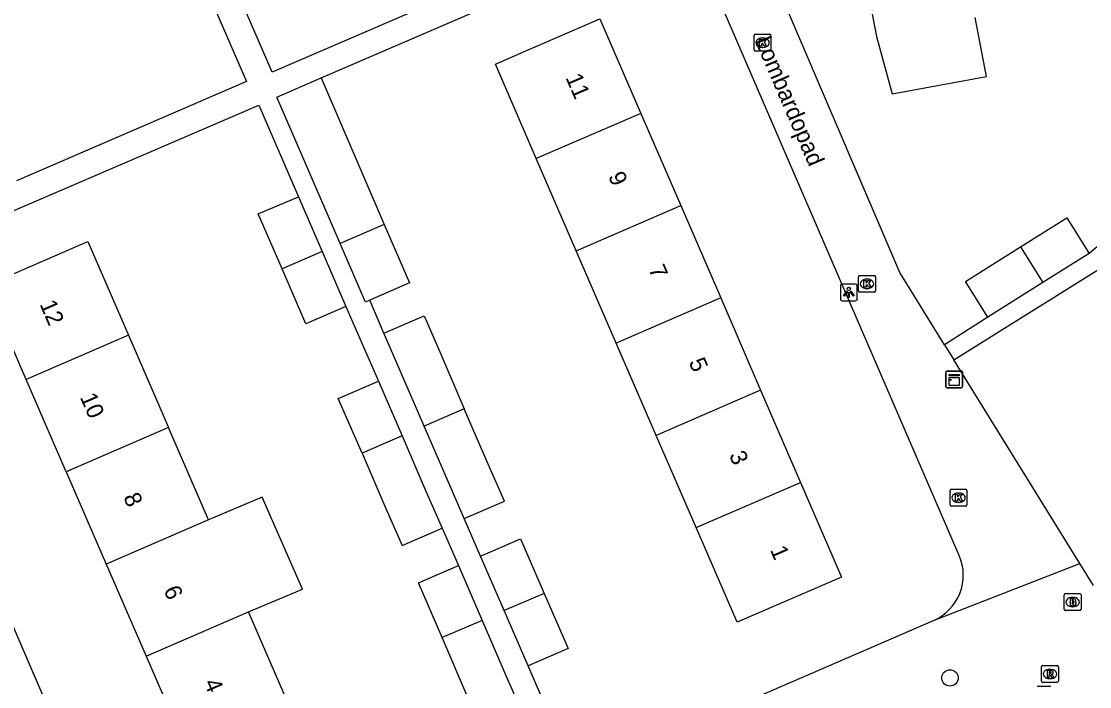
# Model space of a CAD drawing. Extents: x 159353 to 160616, y 385893 to 387321.
# Drawn here: x 159645.1 to 159708.8, y 386260.9 to 386300.6 of the extents above; entities that cross this region are included whole.
import ezdxf

# ---------------------------------------------------------------- set-up
doc = ezdxf.new("R2010")
doc.units = 0
for name, color, linetype in [('IMGEO_Boom', 7, 'Continuous'), ('IMGEO_Brandkraan', 7, 'Continuous'), ('IMGEO_Kast', 7, 'Continuous'), ('IMGEO_Kolk', 7, 'Continuous'), ('IMGEO_Lichtpunt', 7, 'Continuous'), ('IMGEO_Openbare_ruimte_label', 7, 'Continuous'), ('IMGEO_Pand', 7, 'Continuous'), ('IMGEO_Pand_nummerreeks', 7, 'Continuous'), ('IMGEO_Rioolput', 7, 'Continuous'), ('IMGEO_Voetpad_open', 7, 'Continuous')]:
    doc.layers.add(name, color=color, linetype=linetype)

msp = doc.modelspace()

# ---------------------------------------------------------------- linework, layer by layer
at = {"layer": 'IMGEO_Boom'}
msp.add_circle((159700.455, 386261.45), 0.489, dxfattribs=at)
at = {"layer": 'IMGEO_Brandkraan'}
for p, q in [((159707.263, 386265.547), (159707.263, 386266.399)), ((159707.338, 386266.473), (159708.19, 386266.473)), ((159707.751, 386266.253), (159707.776, 386266.253)), ((159708.264, 386266.399), (159708.264, 386265.547)), ((159708.19, 386265.473), (159707.338, 386265.473)), ((159707.774, 386265.693), (159707.749, 386265.693))]:
    msp.add_line(p, q, dxfattribs=at)
for points in [[(159707.263, 386265.547), (159707.263, 386266.399)], [(159707.338, 386266.473), (159708.19, 386266.473)], [(159707.611, 386266.173), (159707.611, 386265.773), (159707.824, 386265.773)], [(159707.842, 386266.173), (159707.611, 386266.173)], [(159707.79, 386266.092), (159707.736, 386266.092), (159707.736, 386266.016)], [(159708.264, 386266.399), (159708.264, 386265.547)], [(159708.19, 386265.473), (159707.338, 386265.473)], [(159707.736, 386266.016), (159707.789, 386266.016)], [(159707.798, 386265.94), (159707.736, 386265.94), (159707.736, 386265.859)], [(159707.736, 386265.859), (159707.798, 386265.859)]]:
    msp.add_lwpolyline(points, dxfattribs=at)
for centre, radius, start, end in [((159707.34, 386266.397), 0.0765, 91.55205, 178.44795), ((159707.34, 386266.397), 0.0765, 91.55205, 178.44795), ((159707.791, 386266.054), 0.0379, 267.82845, 90.93552), ((159707.846, 386266.028), 0.145, 59.4692, 91.53667), ((159707.871, 386266.075), 0.0922, 285.51372, 58.15012), ((159708.188, 386266.397), 0.0765, 1.55205, 88.44795), ((159708.188, 386266.397), 0.0765, 1.55205, 88.44795), ((159707.34, 386265.549), 0.0765, 181.55205, 268.44795), ((159707.34, 386265.549), 0.0765, 181.55205, 268.44795), ((159707.799, 386265.899), 0.0404, 269.87594, 90.50774), ((159707.83, 386266.024), 0.251, 268.66757, 293.53466), ((159707.876, 386265.883), 0.105, 301.31148, 78.98903), ((159708.188, 386265.549), 0.0765, 271.55205, 358.44795), ((159708.188, 386265.549), 0.0765, 271.55205, 358.44795)]:
    msp.add_arc(centre, radius, start, end, dxfattribs=at)
for centre, major_axis, ratio, start_param, end_param in [((159707.75, 386265.973), (-0.387, 0.002), 0.722429, 4.712389, 7.853982), ((159707.775, 386265.973), (-0.39, 0.002), 0.717154, 1.570796, 4.712389)]:
    msp.add_ellipse(centre, major_axis=major_axis, ratio=ratio, start_param=start_param, end_param=end_param, dxfattribs=at)
at = {"layer": 'IMGEO_Kast'}
for p, q in [((159700.204, 386278.825), (159700.204, 386279.666)), ((159700.204, 386279.666), (159700.204, 386278.825)), ((159700.279, 386279.75), (159701.12, 386279.75)), ((159701.12, 386279.75), (159700.279, 386279.75)), ((159701.204, 386279.675), (159701.204, 386278.834)), ((159701.204, 386278.834), (159701.204, 386279.675)), ((159701.129, 386278.75), (159700.288, 386278.75)), ((159700.288, 386278.75), (159701.129, 386278.75))]:
    msp.add_line(p, q, dxfattribs=at)
for points in [[(159700.399, 386279.54), (159700.999, 386279.54), (159700.999, 386279.455), (159700.399, 386279.455), (159700.399, 386279.54)], [(159700.399, 386279.365), (159700.999, 386279.365), (159700.999, 386278.876), (159700.399, 386278.876), (159700.399, 386279.365)]]:
    msp.add_lwpolyline(points, dxfattribs=at)
msp.add_circle((159700.483, 386279.214), 0.0377, dxfattribs=at)
for centre, start, end in [((159700.282, 386279.672), 92.4484, 184.28452), ((159700.282, 386279.672), 92.4484, 184.28452), ((159701.126, 386279.672), 2.4484, 94.28452), ((159701.126, 386279.672), 2.4484, 94.28452), ((159700.282, 386278.828), 182.4484, 274.28452), ((159700.282, 386278.828), 182.4484, 274.28452), ((159701.126, 386278.828), 272.4484, 4.28452), ((159701.126, 386278.828), 272.4484, 4.28452)]:
    msp.add_arc(centre, 0.0779, start, end, dxfattribs=at)
at = {"layer": 'IMGEO_Kolk'}
for p, q in [((159688.854, 386299.828), (159689.706, 386299.828)), ((159688.779, 386298.902), (159688.779, 386299.754)), ((159689.267, 386299.608), (159689.292, 386299.608)), ((159689.78, 386299.754), (159689.78, 386298.902)), ((159689.706, 386298.828), (159688.854, 386298.828)), ((159689.29, 386299.048), (159689.265, 386299.048)), ((159695.005, 386284.521), (159695.005, 386285.373)), ((159695.08, 386285.447), (159695.932, 386285.447)), ((159695.493, 386285.227), (159695.518, 386285.227)), ((159696.006, 386285.373), (159696.006, 386284.521)), ((159695.516, 386284.667), (159695.491, 386284.667)), ((159695.932, 386284.447), (159695.08, 386284.447)), ((159700.461, 386271.769), (159700.461, 386272.621)), ((159700.536, 386272.695), (159701.388, 386272.695)), ((159700.949, 386272.475), (159700.974, 386272.475)), ((159701.462, 386272.621), (159701.462, 386271.769)), ((159700.972, 386271.915), (159700.947, 386271.915)), ((159701.388, 386271.695), (159700.536, 386271.695))]:
    msp.add_line(p, q, dxfattribs=at)
for points in [[(159688.854, 386299.828), (159689.706, 386299.828)], [(159688.779, 386298.902), (159688.779, 386299.754)], [(159689.1, 386299.528), (159689.223, 386299.528), (159689.223, 386299.377), (159689.353, 386299.528), (159689.517, 386299.528), (159689.371, 386299.377), (159689.524, 386299.128), (159689.372, 386299.128), (159689.287, 386299.292), (159689.223, 386299.225), (159689.223, 386299.128), (159689.1, 386299.128), (159689.1, 386299.528)], [(159689.78, 386299.754), (159689.78, 386298.902)], [(159689.706, 386298.828), (159688.854, 386298.828)], [(159695.005, 386284.521), (159695.005, 386285.373)], [(159695.08, 386285.447), (159695.932, 386285.447)], [(159695.326, 386285.147), (159695.449, 386285.147), (159695.449, 386284.996), (159695.579, 386285.147), (159695.743, 386285.147), (159695.597, 386284.996), (159695.75, 386284.747), (159695.598, 386284.747), (159695.513, 386284.911), (159695.449, 386284.844), (159695.449, 386284.747), (159695.326, 386284.747), (159695.326, 386285.147)], [(159696.006, 386285.373), (159696.006, 386284.521)], [(159695.932, 386284.447), (159695.08, 386284.447)], [(159700.461, 386271.769), (159700.461, 386272.621)], [(159700.536, 386272.695), (159701.388, 386272.695)], [(159700.782, 386272.395), (159700.905, 386272.395), (159700.905, 386272.244), (159701.035, 386272.395), (159701.199, 386272.395), (159701.053, 386272.244), (159701.206, 386271.995), (159701.054, 386271.995), (159700.969, 386272.159), (159700.905, 386272.092), (159700.905, 386271.995), (159700.782, 386271.995), (159700.782, 386272.395)], [(159701.462, 386272.621), (159701.462, 386271.769)], [(159701.388, 386271.695), (159700.536, 386271.695)]]:
    msp.add_lwpolyline(points, dxfattribs=at)
for centre, start, end in [((159688.856, 386299.752), 91.55205, 178.44795), ((159688.856, 386299.752), 91.55205, 178.44795), ((159689.704, 386299.752), 1.55205, 88.44795), ((159689.704, 386299.752), 1.55205, 88.44795), ((159688.856, 386298.904), 181.55205, 268.44795), ((159688.856, 386298.904), 181.55205, 268.44795), ((159689.704, 386298.904), 271.55205, 358.44795), ((159689.704, 386298.904), 271.55205, 358.44795), ((159695.082, 386285.371), 91.55205, 178.44795), ((159695.082, 386285.371), 91.55205, 178.44795), ((159695.93, 386285.371), 1.55205, 88.44795), ((159695.93, 386285.371), 1.55205, 88.44795), ((159695.082, 386284.523), 181.55205, 268.44795), ((159695.082, 386284.523), 181.55205, 268.44795), ((159695.93, 386284.523), 271.55205, 358.44795), ((159695.93, 386284.523), 271.55205, 358.44795), ((159700.538, 386272.619), 91.55205, 178.44795), ((159700.538, 386272.619), 91.55205, 178.44795), ((159701.386, 386272.619), 1.55205, 88.44795), ((159701.386, 386272.619), 1.55205, 88.44795), ((159700.538, 386271.771), 181.55205, 268.44795), ((159700.538, 386271.771), 181.55205, 268.44795), ((159701.386, 386271.771), 271.55205, 358.44795), ((159701.386, 386271.771), 271.55205, 358.44795)]:
    msp.add_arc(centre, 0.0765, start, end, dxfattribs=at)
for centre, major_axis, ratio, start_param, end_param in [((159689.266, 386299.328), (-0.387, 0.002), 0.722429, 4.712389, 7.853982), ((159689.291, 386299.328), (-0.39, 0.002), 0.717154, 1.570796, 4.712389), ((159695.492, 386284.947), (-0.387, 0.002), 0.722429, 4.712389, 7.853982), ((159695.517, 386284.947), (-0.39, 0.002), 0.717154, 1.570796, 4.712389), ((159700.948, 386272.195), (-0.387, 0.002), 0.722429, 4.712389, 7.853982), ((159700.973, 386272.195), (-0.39, 0.002), 0.717154, 1.570796, 4.712389)]:
    msp.add_ellipse(centre, major_axis=major_axis, ratio=ratio, start_param=start_param, end_param=end_param, dxfattribs=at)
at = {"layer": 'IMGEO_Lichtpunt'}
for p, q in [((159693.924, 386284.842), (159693.924, 386284.035)), ((159693.924, 386284.842), (159693.924, 386284.035)), ((159694.826, 386284.937), (159694.018, 386284.937)), ((159694.826, 386284.937), (159694.018, 386284.937)), ((159694.92, 386284.035), (159694.92, 386284.842)), ((159694.92, 386284.035), (159694.92, 386284.842)), ((159694.018, 386283.941), (159694.826, 386283.941)), ((159694.018, 386283.941), (159694.826, 386283.941)), ((159706.455, 386260.928), (159705.647, 386260.928)), ((159706.455, 386260.928), (159705.647, 386260.928))]:
    msp.add_line(p, q, dxfattribs=at)
for points in [[(159694.298, 386284.506), (159694.337, 386284.478), (159694.149, 386284.216), (159694.111, 386284.243), (159694.298, 386284.506)], [(159694.51, 386284.478), (159694.548, 386284.505), (159694.735, 386284.243), (159694.696, 386284.215), (159694.51, 386284.478)], [(159694.4, 386284.458), (159694.447, 386284.458), (159694.447, 386284.136), (159694.4, 386284.136), (159694.4, 386284.458)]]:
    msp.add_lwpolyline(points, dxfattribs=at)
msp.add_circle((159694.423, 386284.64), 0.0994, dxfattribs=at)
for centre, start, end in [((159694.018, 386284.842), 90, 180), ((159694.018, 386284.842), 90, 180), ((159694.826, 386284.842), 0, 90), ((159694.826, 386284.842), 0, 90), ((159694.018, 386284.035), 180, 270), ((159694.018, 386284.035), 180, 270), ((159694.826, 386284.035), 270, 0), ((159694.826, 386284.035), 270, 360)]:
    msp.add_arc(centre, 0.0946, start, end, dxfattribs=at)
at = {"layer": 'IMGEO_Pand'}
for points in [[(159700.678, 386307.441), (159694.802, 386306.304), (159696.082, 386299.697), (159697, 386296.28), (159702.621, 386297.319), (159701.958, 386300.826)], [(159675.796, 386292.416), (159673.355, 386298.054), (159674.994, 386298.764), (159679.582, 386300.75), (159682.023, 386295.112)], [(159664.109, 386287.356), (159660.337, 386296.088), (159662.967, 386297.224)], [(159662.967, 386297.224), (159666.737, 386288.494)], [(159682.023, 386295.112), (159675.796, 386292.416)], [(159682.023, 386295.112), (159684.404, 386289.61)], [(159678.178, 386286.914), (159675.796, 386292.416)], [(159660.638, 386285.851), (159659.226, 386289.113), (159661.612, 386290.145)], [(159661.612, 386290.145), (159663.023, 386286.884)], [(159678.178, 386286.914), (159684.404, 386289.61)], [(159684.404, 386289.61), (159686.786, 386284.108)], [(159666.737, 386288.494), (159664.109, 386287.356)], [(159666.737, 386288.494), (159668.247, 386284.999), (159665.868, 386283.972)], [(159704.664, 386287.155), (159707.422, 386288.882), (159708.755, 386286.755)], [(159645.381, 386279.239), (159642.958, 386284.827), (159647.546, 386286.816), (159649.064, 386287.474), (159651.487, 386281.885)], [(159665.868, 386283.972), (159665.617, 386283.864), (159664.109, 386287.356)], [(159702.704, 386282.965), (159701.371, 386285.092), (159704.664, 386287.155)], [(159704.664, 386287.155), (159705.997, 386285.027)], [(159663.023, 386286.884), (159660.638, 386285.851)], [(159663.023, 386286.884), (159664.448, 386283.593)], [(159680.559, 386281.413), (159678.178, 386286.914)], [(159708.755, 386286.755), (159705.997, 386285.027)], [(159664.448, 386283.593), (159662.062, 386282.561), (159660.638, 386285.851)], [(159705.997, 386285.027), (159702.704, 386282.965)], [(159686.786, 386284.108), (159680.559, 386281.413)], [(159686.786, 386284.108), (159689.167, 386278.607)], [(159666.716, 386282.012), (159669.102, 386283.045), (159670.095, 386280.751), (159671.505, 386277.494)], [(159669.119, 386276.462), (159667.709, 386279.718), (159666.716, 386282.012)], [(159651.487, 386281.885), (159645.381, 386279.239)], [(159651.487, 386281.885), (159653.872, 386276.384)], [(159682.941, 386275.911), (159680.559, 386281.413)], [(159647.765, 386273.739), (159645.381, 386279.239)], [(159665.407, 386274.85), (159663.995, 386278.112), (159666.381, 386279.144)], [(159666.381, 386279.144), (159667.792, 386275.883)], [(159689.167, 386278.607), (159682.941, 386275.911)], [(159689.167, 386278.607), (159691.549, 386273.105)], [(159671.505, 386277.494), (159669.119, 386276.462)], [(159671.504, 386270.951), (159673.89, 386271.984), (159672.931, 386274.199), (159671.505, 386277.494)], [(159653.872, 386276.384), (159647.765, 386273.739)], [(159656.256, 386270.884), (159653.872, 386276.384)], [(159671.504, 386270.951), (159670.545, 386273.166), (159669.119, 386276.462)], [(159667.792, 386275.883), (159665.407, 386274.85)], [(159667.792, 386275.883), (159669.217, 386272.592), (159670.178, 386270.372)], [(159685.322, 386270.41), (159682.941, 386275.911)], [(159665.407, 386274.85), (159666.831, 386271.56), (159667.793, 386269.339), (159670.178, 386270.372)], [(159647.765, 386273.739), (159650.15, 386268.238)], [(159691.549, 386273.105), (159693.99, 386267.465), (159687.764, 386264.77), (159685.777, 386269.359), (159685.322, 386270.41)], [(159685.322, 386270.41), (159691.549, 386273.105)], [(159658.641, 386265.383), (159661.859, 386266.75), (159659.462, 386272.227), (159656.256, 386270.884)], [(159656.256, 386270.884), (159650.15, 386268.238)], [(159672.472, 386268.715), (159674.858, 386269.748), (159676.268, 386266.491)], [(159673.882, 386265.459), (159672.472, 386268.715)], [(159650.15, 386268.238), (159652.534, 386262.738)], [(159670.176, 386263.849), (159668.764, 386267.111), (159671.15, 386268.143)], [(159671.15, 386268.143), (159672.561, 386264.882)], [(159676.268, 386266.491), (159673.882, 386265.459)], [(159676.268, 386266.491), (159677.694, 386263.196), (159675.308, 386262.163)], [(159675.308, 386262.163), (159673.882, 386265.459)], [(159652.534, 386262.738), (159658.641, 386265.383)], [(159661.025, 386259.883), (159658.641, 386265.383)], [(159672.561, 386264.882), (159670.176, 386263.849)], [(159672.561, 386264.882), (159673.986, 386261.591), (159676.792, 386255.192)], [(159676.792, 386255.192), (159674.437, 386254.151), (159671.6, 386260.559), (159670.176, 386263.849)], [(159652.534, 386262.738), (159654.919, 386257.237)]]:
    msp.add_lwpolyline(points, dxfattribs=at)
at = {"layer": 'IMGEO_Rioolput'}
for p, q in [((159705.911, 386261.258), (159705.911, 386262.11)), ((159705.986, 386262.184), (159706.838, 386262.184)), ((159706.399, 386261.964), (159706.424, 386261.964)), ((159706.912, 386262.11), (159706.912, 386261.258)), ((159706.838, 386261.184), (159705.986, 386261.184)), ((159706.422, 386261.404), (159706.397, 386261.404))]:
    msp.add_line(p, q, dxfattribs=at)
for points in [[(159705.911, 386261.258), (159705.911, 386262.11)], [(159705.986, 386262.184), (159706.838, 386262.184)], [(159706.5, 386261.882), (159706.248, 386261.884), (159706.248, 386261.484)], [(159706.248, 386261.484), (159706.372, 386261.484), (159706.372, 386261.646), (159706.383, 386261.646)], [(159706.426, 386261.803), (159706.372, 386261.803), (159706.372, 386261.722)], [(159706.372, 386261.722), (159706.424, 386261.722)], [(159706.43, 386261.617), (159706.501, 386261.484), (159706.641, 386261.484), (159706.576, 386261.61)], [(159706.912, 386262.11), (159706.912, 386261.258)], [(159706.838, 386261.184), (159705.986, 386261.184)]]:
    msp.add_lwpolyline(points, dxfattribs=at)
for centre, radius, start, end in [((159705.988, 386262.108), 0.0765, 91.55205, 178.44795), ((159705.988, 386262.108), 0.0765, 91.55205, 178.44795), ((159706.382, 386261.593), 0.0533, 26.02933, 88.69889), ((159706.408, 386261.911), 0.19, 274.7715, 282.96867), ((159706.432, 386261.707), 0.0964, 77.00612, 93.18647), ((159706.446, 386261.764), 0.0378, 276.66336, 79.67722), ((159706.499, 386261.772), 0.109, 350.36119, 89.41601), ((159706.497, 386261.772), 0.112, 277.58423, 350.98172), ((159706.481, 386261.557), 0.108, 29.51342, 73.79051), ((159706.836, 386262.108), 0.0765, 1.55205, 88.44795), ((159706.836, 386262.108), 0.0765, 1.55205, 88.44795), ((159705.988, 386261.26), 0.0765, 181.55205, 268.44795), ((159705.988, 386261.26), 0.0765, 181.55205, 268.44795), ((159706.836, 386261.26), 0.0765, 271.55205, 358.44795), ((159706.836, 386261.26), 0.0765, 271.55205, 358.44795)]:
    msp.add_arc(centre, radius, start, end, dxfattribs=at)
for centre, major_axis, ratio, start_param, end_param in [((159706.398, 386261.684), (-0.387, 0.002), 0.722429, 4.712389, 7.853982), ((159706.423, 386261.684), (-0.39, 0.002), 0.717154, 1.570796, 4.712389)]:
    msp.add_ellipse(centre, major_axis=major_axis, ratio=ratio, start_param=start_param, end_param=end_param, dxfattribs=at)
at = {"layer": 'IMGEO_Voetpad_open'}
for points in [[(159684.092, 386307.943), (159660.056, 386297.569), (159659.735, 386298.309), (159657.843, 386302.678)], [(159662.967, 386297.224), (159684.675, 386306.593)], [(159701.006, 386268.753), (159684.675, 386306.593)], [(159700.131, 386281.311), (159697.471, 386285.615), (159689.082, 386305.236)], [(159656.34, 386302.053), (159658.516, 386297.013), (159644.802, 386291.091)], [(159635.593, 386285.426), (159659.247, 386295.61), (159661.612, 386290.145)], [(159712.133, 386289.552), (159708.755, 386286.755)], [(159700.683, 386280.417), (159711.275, 386287.034)], [(159635.593, 386285.426), (159650.846, 386250), (159651.931, 386247.481)], [(159666.716, 386282.012), (159665.868, 386283.972)], [(159664.448, 386283.593), (159666.381, 386279.144)], [(159702.704, 386282.965), (159700.131, 386281.311)], [(159700.131, 386281.311), (159700.683, 386280.417)], [(159708.189, 386268.272), (159700.683, 386280.417)], [(159672.472, 386268.715), (159671.504, 386270.951)], [(159670.178, 386270.372), (159671.15, 386268.143)], [(159699.462, 386264.867), (159708.189, 386268.272)], [(159709.001, 386266.959), (159708.189, 386268.272)], [(159678.131, 386255.638), (159699.462, 386264.867)], [(159678.131, 386255.638), (159675.308, 386262.163)]]:
    msp.add_lwpolyline(points, dxfattribs=at)
msp.add_arc((159698.292, 386267.582), 2.956, 293.31902, 23.34278, dxfattribs=at)

# ---------------------------------------------------------------- texts
at = {"layer": 'IMGEO_Openbare_ruimte_label'}
msp.add_text('Lombardopad', height=1, rotation=293.33404, dxfattribs=at).set_placement((159688.808, 386299.451))
at = {"layer": 'IMGEO_Pand_nummerreeks'}
for s, rotation, p in [('11', 293.40622, (159677.526, 386297.243)), ('9', 293.40622, (159680.065, 386291.378)), ('7', 293.40622, (159682.466, 386285.83)), ('12', 293.43769, (159646.177, 386283.737)), ('5', 293.40622, (159684.867, 386280.283)), ('10', 293.43769, (159648.58, 386278.193)), ('3', 293.40622, (159687.269, 386274.735)), ('8', 293.43769, (159651.164, 386272.233)), ('1', 293.40622, (159689.715, 386269.084)), ('6', 293.43949, (159653.565, 386266.698)), ('4', 293.43769, (159655.964, 386261.16))]:
    msp.add_text(s, height=1, rotation=rotation, dxfattribs=at).set_placement(p)

doc.saveas('drawing.dxf')
